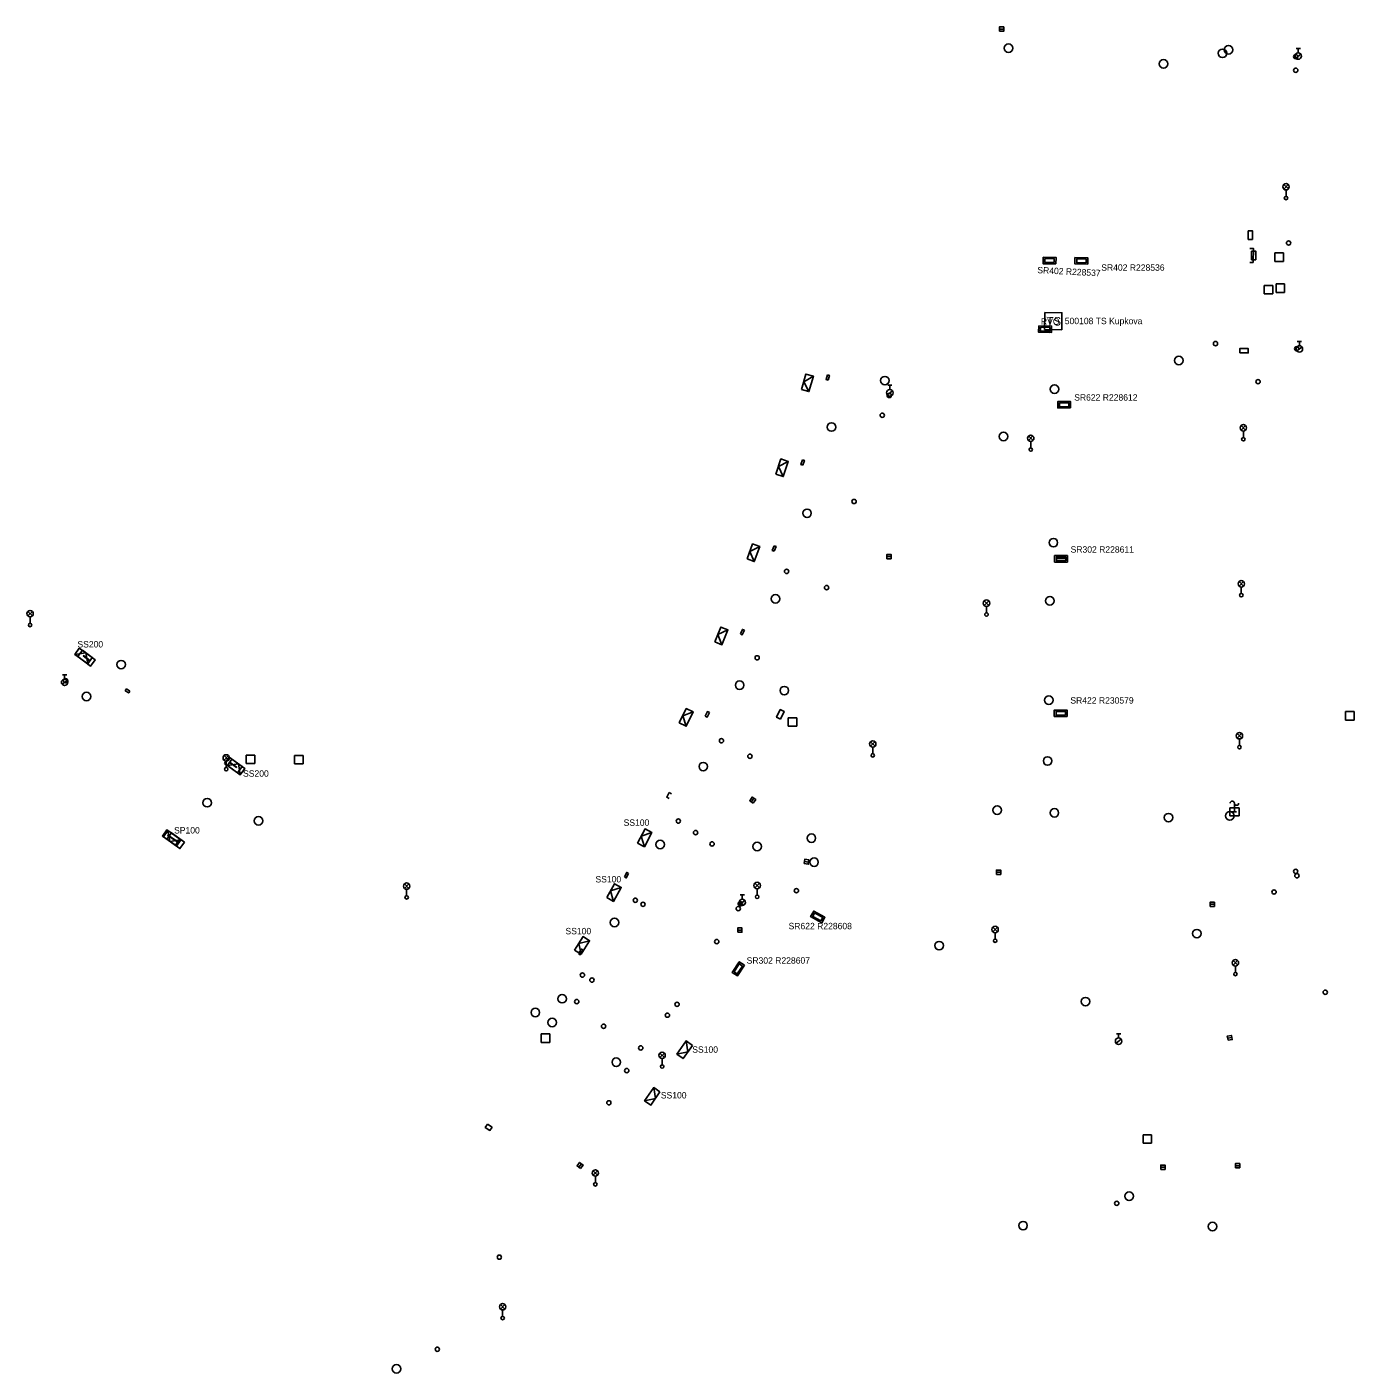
# Model space of a CAD drawing. Extents: x -584388 to -581645, y -1210859 to -1208922.
# Drawn here: x -583175 to -583019.6, y -1210565.7 to -1210408.1 of the extents above; entities that cross this region are included whole.
import ezdxf

# ---------------------------------------------------------------- set-up
doc = ezdxf.new("R2010")
doc.units = 0
for name, color, linetype in [('CIZÍ_NADZEM', 7, 'Continuous'), ('CIZÍ_PODZEM', 7, 'Continuous'), ('ELE_EON', 7, 'Continuous'), ('ELE_EON_POPIS', 7, 'Continuous')]:
    doc.layers.add(name, color=color, linetype=linetype)

msp = doc.modelspace()

# ---------------------------------------------------------------- linework, layer by layer
at = {"layer": 'CIZÍ_NADZEM'}
for p, q in [((-583061.11, -1210408.37), (-583060.61, -1210408.37)), ((-583026.37, -1210410.66), (-583025.87, -1210410.66)), ((-583026.12, -1210411.16), (-583026.12, -1210410.66)), ((-583026.41, -1210411.76), (-583025.82, -1210411.3)), ((-583027.81, -1210427.1), (-583027.29, -1210426.57)), ((-583027.28, -1210427.09), (-583027.81, -1210426.57)), ((-583027.55, -1210427.21), (-583027.55, -1210427.96)), ((-583027.86, -1210434.58), (-583028.86, -1210434.58)), ((-583028.86, -1210434.58), (-583028.86, -1210435.58)), ((-583027.86, -1210435.58), (-583027.86, -1210434.58)), ((-583028.86, -1210435.58), (-583027.86, -1210435.58)), ((-583029.11, -1210438.38), (-583030.11, -1210438.38)), ((-583030.11, -1210438.38), (-583030.11, -1210439.38)), ((-583030.11, -1210439.38), (-583029.11, -1210439.38)), ((-583029.11, -1210439.38), (-583029.11, -1210438.38)), ((-583027.72, -1210438.2), (-583028.72, -1210438.2)), ((-583028.72, -1210438.2), (-583028.72, -1210439.2)), ((-583028.72, -1210439.2), (-583027.72, -1210439.2)), ((-583027.72, -1210439.2), (-583027.72, -1210438.2)), ((-583026.27, -1210446.05), (-583025.68, -1210445.59)), ((-583026.23, -1210444.95), (-583025.73, -1210444.95)), ((-583025.98, -1210445.45), (-583025.98, -1210444.95)), ((-583074.2, -1210450.08), (-583073.7, -1210450.08)), ((-583073.95, -1210450.58), (-583073.95, -1210450.08)), ((-583074.24, -1210451.19), (-583073.65, -1210450.73)), ((-583032.81, -1210455.33), (-583032.29, -1210454.8)), ((-583032.28, -1210455.32), (-583032.81, -1210454.8)), ((-583057.71, -1210456.54), (-583057.19, -1210456.01)), ((-583057.18, -1210456.54), (-583057.71, -1210456.01)), ((-583057.45, -1210456.65), (-583057.45, -1210457.4)), ((-583032.55, -1210455.44), (-583032.55, -1210456.19)), ((-583074.3, -1210470.13), (-583073.8, -1210470.13)), ((-583033.05, -1210473.59), (-583032.53, -1210473.06)), ((-583032.52, -1210473.58), (-583033.05, -1210473.06)), ((-583032.79, -1210473.7), (-583032.79, -1210474.45)), ((-583062.89, -1210475.85), (-583062.37, -1210475.32)), ((-583062.36, -1210475.84), (-583062.89, -1210475.32)), ((-583174.9, -1210477.08), (-583174.38, -1210476.55)), ((-583174.37, -1210477.07), (-583174.9, -1210476.55)), ((-583174.64, -1210477.19), (-583174.64, -1210477.94)), ((-583062.63, -1210475.96), (-583062.63, -1210476.71)), ((-583170.89, -1210485.08), (-583170.3, -1210484.62)), ((-583170.85, -1210483.98), (-583170.35, -1210483.98)), ((-583170.6, -1210484.48), (-583170.6, -1210483.98)), ((-583020.58, -1210488.27), (-583020.58, -1210489.27)), ((-583019.58, -1210488.27), (-583020.58, -1210488.27)), ((-583019.58, -1210489.27), (-583019.58, -1210488.27)), ((-583084.86, -1210489), (-583085.86, -1210489)), ((-583085.86, -1210489), (-583085.86, -1210490)), ((-583085.86, -1210490), (-583084.86, -1210490)), ((-583084.86, -1210490), (-583084.86, -1210489)), ((-583020.58, -1210489.27), (-583019.58, -1210489.27)), ((-583033.27, -1210491.38), (-583032.75, -1210490.85)), ((-583032.74, -1210491.38), (-583033.27, -1210490.85)), ((-583033.01, -1210491.49), (-583033.01, -1210492.24)), ((-583076.21, -1210492.34), (-583075.69, -1210491.81)), ((-583075.68, -1210492.33), (-583076.21, -1210491.81)), ((-583075.95, -1210492.45), (-583075.95, -1210493.2)), ((-583151.93, -1210493.96), (-583151.41, -1210493.43)), ((-583151.4, -1210493.96), (-583151.93, -1210493.43)), ((-583151.67, -1210494.07), (-583151.67, -1210494.82)), ((-583148.34, -1210493.36), (-583149.34, -1210493.36)), ((-583149.34, -1210493.36), (-583149.34, -1210494.36)), ((-583149.34, -1210494.36), (-583148.34, -1210494.36)), ((-583148.34, -1210494.36), (-583148.34, -1210493.36)), ((-583142.68, -1210493.41), (-583143.68, -1210493.41)), ((-583143.68, -1210493.41), (-583143.68, -1210494.41)), ((-583143.68, -1210494.41), (-583142.68, -1210494.41)), ((-583142.68, -1210494.41), (-583142.68, -1210493.41)), ((-583090.15, -1210498.85), (-583089.87, -1210498.43)), ((-583033.6, -1210500), (-583033.6, -1210499)), ((-583033.85, -1210500), (-583033.35, -1210500)), ((-583083.96, -1210505.82), (-583083.46, -1210505.9)), ((-583061.46, -1210507.09), (-583060.96, -1210507.09)), ((-583130.8, -1210508.97), (-583130.28, -1210508.44)), ((-583130.27, -1210508.97), (-583130.8, -1210508.44)), ((-583089.75, -1210508.9), (-583089.23, -1210508.37)), ((-583089.22, -1210508.9), (-583089.75, -1210508.37)), ((-583130.54, -1210509.08), (-583130.54, -1210509.83)), ((-583091.52, -1210510.84), (-583090.93, -1210510.38)), ((-583091.48, -1210509.74), (-583090.98, -1210509.74)), ((-583091.23, -1210510.24), (-583091.23, -1210509.74)), ((-583089.49, -1210509.01), (-583089.49, -1210509.76)), ((-583036.44, -1210510.84), (-583035.94, -1210510.84)), ((-583061.88, -1210514.05), (-583061.36, -1210513.52)), ((-583061.35, -1210514.05), (-583061.88, -1210513.52)), ((-583091.77, -1210513.86), (-583091.27, -1210513.86)), ((-583061.62, -1210514.16), (-583061.62, -1210514.91)), ((-583033.74, -1210517.95), (-583033.22, -1210517.42)), ((-583033.21, -1210517.95), (-583033.74, -1210517.42)), ((-583033.48, -1210518.06), (-583033.48, -1210518.81)), ((-583113.77, -1210526.01), (-583114.77, -1210526.01)), ((-583114.77, -1210526.01), (-583114.77, -1210527.01)), ((-583113.77, -1210527.01), (-583113.77, -1210526.01)), ((-583047.41, -1210525.99), (-583046.91, -1210525.99)), ((-583047.16, -1210526.49), (-583047.16, -1210525.99)), ((-583114.77, -1210527.01), (-583113.77, -1210527.01)), ((-583047.45, -1210527.09), (-583046.86, -1210526.63)), ((-583034.39, -1210526.52), (-583033.89, -1210526.42)), ((-583100.88, -1210528.78), (-583100.36, -1210528.25)), ((-583100.35, -1210528.78), (-583100.88, -1210528.25)), ((-583100.62, -1210528.89), (-583100.62, -1210529.64)), ((-583043.29, -1210537.82), (-583044.29, -1210537.82)), ((-583044.29, -1210537.82), (-583044.29, -1210538.82)), ((-583044.29, -1210538.82), (-583043.29, -1210538.82)), ((-583043.29, -1210538.82), (-583043.29, -1210537.82)), ((-583110.38, -1210541.61), (-583110.08, -1210541.21)), ((-583108.7, -1210542.56), (-583108.18, -1210542.03)), ((-583108.17, -1210542.56), (-583108.7, -1210542.03)), ((-583042.22, -1210541.62), (-583041.72, -1210541.62)), ((-583033.48, -1210541.44), (-583032.98, -1210541.44)), ((-583108.44, -1210542.67), (-583108.44, -1210543.42)), ((-583119.56, -1210558.22), (-583119.04, -1210557.69)), ((-583119.03, -1210558.22), (-583119.56, -1210557.69)), ((-583119.3, -1210558.33), (-583119.3, -1210559.08))]:
    msp.add_line(p, q, dxfattribs=at)
for points in [[(-583061.11, -1210408.62), (-583060.61, -1210408.62), (-583060.61, -1210408.12), (-583061.11, -1210408.12)], [(-583031.47, -1210433), (-583031.47, -1210432), (-583031.97, -1210432), (-583031.97, -1210433)], [(-583031.08, -1210435.38), (-583031.08, -1210434.38), (-583031.58, -1210434.38), (-583031.58, -1210435.38)], [(-583032.97, -1210446.28), (-583031.97, -1210446.28), (-583031.97, -1210445.78), (-583032.97, -1210445.78)], [(-583074.3, -1210470.38), (-583073.8, -1210470.38), (-583073.8, -1210469.88), (-583074.3, -1210469.88)], [(-583086.77, -1210489.16), (-583086.34, -1210488.26), (-583086.79, -1210488.04), (-583087.22, -1210488.94)], [(-583089.94, -1210498.99), (-583089.66, -1210498.57), (-583090.08, -1210498.29), (-583090.36, -1210498.71)], [(-583084, -1210506.07), (-583083.5, -1210506.15), (-583083.42, -1210505.65), (-583083.92, -1210505.57)], [(-583061.46, -1210507.34), (-583060.96, -1210507.34), (-583060.96, -1210506.84), (-583061.46, -1210506.84)], [(-583036.44, -1210511.09), (-583035.94, -1210511.09), (-583035.94, -1210510.59), (-583036.44, -1210510.59)], [(-583091.77, -1210514.11), (-583091.27, -1210514.11), (-583091.27, -1210513.61), (-583091.77, -1210513.61)], [(-583034.34, -1210526.76), (-583033.85, -1210526.67), (-583033.94, -1210526.18), (-583034.43, -1210526.27)], [(-583110.18, -1210541.76), (-583109.88, -1210541.36), (-583110.28, -1210541.06), (-583110.58, -1210541.46)], [(-583042.22, -1210541.87), (-583041.72, -1210541.87), (-583041.72, -1210541.37), (-583042.22, -1210541.37)], [(-583033.48, -1210541.69), (-583032.98, -1210541.69), (-583032.98, -1210541.19), (-583033.48, -1210541.19)]]:
    msp.add_lwpolyline(points, close=True, dxfattribs=at)
for points in [[(-583031.38, -1210435.71), (-583031.37, -1210434.05), (-583031.78, -1210434.05)], [(-583031.38, -1210435.71), (-583031.79, -1210435.71)], [(-583056.31, -1210443.54), (-583056.32, -1210443.86), (-583055.25, -1210443.89)], [(-583055.24, -1210443.56), (-583055.25, -1210443.89)], [(-583081.26, -1210448.85), (-583081.42, -1210449.4), (-583081.18, -1210449.47)], [(-583081.26, -1210448.85), (-583081.02, -1210448.92), (-583081.18, -1210449.47)], [(-583084.19, -1210458.79), (-583084.37, -1210459.35), (-583084.13, -1210459.43)], [(-583084.19, -1210458.79), (-583083.95, -1210458.87), (-583084.13, -1210459.43)], [(-583087.51, -1210468.87), (-583087.72, -1210469.41), (-583087.49, -1210469.5)], [(-583087.51, -1210468.87), (-583087.28, -1210468.96), (-583087.49, -1210469.5)], [(-583054.36, -1210470.36), (-583054.36, -1210470.01)], [(-583053.27, -1210470.02), (-583054.36, -1210470.01)], [(-583053.27, -1210470.37), (-583054.36, -1210470.36)], [(-583091.46, -1210479.19), (-583091.22, -1210478.65), (-583090.99, -1210478.75)], [(-583091.46, -1210479.19), (-583091.23, -1210479.29), (-583090.99, -1210478.75)], [(-583095.57, -1210488.82), (-583095.31, -1210488.28), (-583095.09, -1210488.39)], [(-583095.57, -1210488.82), (-583095.35, -1210488.93), (-583095.09, -1210488.39)], [(-583099.79, -1210497.75), (-583100.07, -1210498.3), (-583099.79, -1210498.44)], [(-583099.79, -1210497.75), (-583099.51, -1210497.89)], [(-583105.04, -1210507.62), (-583104.76, -1210507.1), (-583104.54, -1210507.22)], [(-583105.04, -1210507.62), (-583104.82, -1210507.74), (-583104.54, -1210507.22)], [(-583110.41, -1210516.61), (-583110.08, -1210516.09), (-583109.87, -1210516.22)], [(-583110.41, -1210516.61), (-583110.2, -1210516.74), (-583109.87, -1210516.22)]]:
    msp.add_lwpolyline(points, dxfattribs=at)
for centre, radius in [((-583060.05, -1210410.61), 0.5), ((-583034.99, -1210411.21), 0.5), ((-583034.29, -1210410.79), 0.5), ((-583026.12, -1210411.53), 0.375), ((-583041.89, -1210412.45), 0.5), ((-583026.42, -1210411.59), 0.25), ((-583026.41, -1210413.19), 0.25), ((-583027.55, -1210426.83), 0.375), ((-583027.55, -1210428.16), 0.2), ((-583027.25, -1210433.42), 0.25), ((-583035.81, -1210445.19), 0.25), ((-583026.3, -1210445.8), 0.25), ((-583025.98, -1210445.82), 0.375), ((-583040.11, -1210447.17), 0.5), ((-583074.53, -1210449.53), 0.5), ((-583073.95, -1210450.96), 0.375), ((-583054.67, -1210450.52), 0.5), ((-583030.82, -1210449.65), 0.25), ((-583074.02, -1210451.27), 0.25), ((-583074.84, -1210453.58), 0.25), ((-583080.78, -1210454.96), 0.5), ((-583032.55, -1210455.06), 0.375), ((-583060.64, -1210456.06), 0.5), ((-583057.45, -1210456.28), 0.375), ((-583032.55, -1210456.39), 0.2), ((-583057.45, -1210457.6), 0.2), ((-583083.65, -1210465.06), 0.5), ((-583078.14, -1210463.68), 0.25), ((-583054.8, -1210468.5), 0.5), ((-583086.04, -1210471.86), 0.25), ((-583081.36, -1210473.76), 0.25), ((-583032.79, -1210473.32), 0.375), ((-583087.35, -1210475.08), 0.5), ((-583062.63, -1210475.58), 0.375), ((-583055.21, -1210475.3), 0.5), ((-583032.79, -1210474.65), 0.2), ((-583174.64, -1210476.81), 0.375), ((-583062.63, -1210476.91), 0.2), ((-583174.64, -1210478.14), 0.2), ((-583089.49, -1210481.98), 0.25), ((-583163.98, -1210482.78), 0.5), ((-583170.6, -1210484.85), 0.375), ((-583170.49, -1210484.66), 0.25), ((-583091.54, -1210485.19), 0.5), ((-583168.04, -1210486.51), 0.5), ((-583086.31, -1210485.82), 0.5), ((-583055.34, -1210486.94), 0.5), ((-583093.67, -1210491.69), 0.25), ((-583033.01, -1210491.11), 0.375), ((-583075.95, -1210492.07), 0.375), ((-583033.01, -1210492.44), 0.2), ((-583151.67, -1210493.7), 0.375), ((-583095.8, -1210494.72), 0.5), ((-583090.34, -1210493.5), 0.25), ((-583075.95, -1210493.4), 0.2), ((-583055.47, -1210494.06), 0.5), ((-583151.67, -1210495.02), 0.2), ((-583153.9, -1210498.94), 0.5), ((-583061.37, -1210499.81), 0.5), ((-583147.89, -1210501.06), 0.5), ((-583098.72, -1210501.1), 0.25), ((-583054.68, -1210500.13), 0.5), ((-583041.31, -1210500.69), 0.5), ((-583034.14, -1210500.49), 0.5), ((-583096.7, -1210502.44), 0.25), ((-583083.14, -1210503.1), 0.5), ((-583100.86, -1210503.83), 0.5), ((-583094.77, -1210503.77), 0.25), ((-583089.48, -1210504.07), 0.5), ((-583082.83, -1210505.9), 0.5), ((-583026.42, -1210506.99), 0.25), ((-583026.28, -1210507.5), 0.25), ((-583130.54, -1210508.71), 0.375), ((-583089.49, -1210508.64), 0.375), ((-583130.54, -1210510.03), 0.2), ((-583103.76, -1210510.36), 0.25), ((-583091.23, -1210510.61), 0.375), ((-583089.49, -1210509.96), 0.2), ((-583084.89, -1210509.24), 0.25), ((-583028.95, -1210509.4), 0.25), ((-583102.86, -1210510.84), 0.25), ((-583091.71, -1210511.34), 0.25), ((-583091.47, -1210510.78), 0.25), ((-583106.2, -1210512.96), 0.5), ((-583061.62, -1210513.79), 0.375), ((-583094.22, -1210515.2), 0.25), ((-583068.18, -1210515.68), 0.5), ((-583061.62, -1210515.11), 0.2), ((-583037.99, -1210514.27), 0.5), ((-583033.48, -1210517.69), 0.375), ((-583109.95, -1210519.13), 0.25), ((-583108.84, -1210519.71), 0.25), ((-583033.48, -1210519.01), 0.2), ((-583112.33, -1210521.89), 0.5), ((-583022.96, -1210521.13), 0.25), ((-583115.47, -1210523.5), 0.5), ((-583110.62, -1210522.23), 0.25), ((-583098.87, -1210522.55), 0.25), ((-583051.03, -1210522.23), 0.5), ((-583113.5, -1210524.67), 0.5), ((-583100, -1210523.82), 0.25), ((-583107.48, -1210525.12), 0.25), ((-583103.12, -1210527.65), 0.25), ((-583047.16, -1210526.86), 0.375), ((-583105.99, -1210529.33), 0.5), ((-583100.62, -1210528.52), 0.375), ((-583104.76, -1210530.31), 0.25), ((-583100.62, -1210529.84), 0.2), ((-583106.86, -1210534.08), 0.25), ((-583108.44, -1210542.3), 0.375), ((-583108.44, -1210543.62), 0.2), ((-583045.93, -1210545.02), 0.5), ((-583047.38, -1210545.85), 0.25), ((-583058.35, -1210548.46), 0.5), ((-583036.16, -1210548.57), 0.5), ((-583119.69, -1210552.15), 0.25), ((-583119.3, -1210557.96), 0.375), ((-583119.3, -1210559.28), 0.2), ((-583126.95, -1210562.93), 0.25), ((-583131.73, -1210565.22), 0.5)]:
    msp.add_circle(centre, radius, dxfattribs=at)
for centre, start, end in [((-583033.85, -1210499), 0, 180), ((-583033.35, -1210499), 180, 0)]:
    msp.add_arc(centre, 0.25, start, end, dxfattribs=at)
at = {"layer": 'CIZÍ_PODZEM'}
for points in [[(-583163.49, -1210485.83), (-583163.35, -1210485.62), (-583162.95, -1210485.89)], [(-583163.49, -1210485.83), (-583163.09, -1210486.1), (-583162.95, -1210485.89)], [(-583034.15, -1210499.55), (-583033.05, -1210499.53)], [(-583034.15, -1210499.55), (-583034.14, -1210500.49)], [(-583033.04, -1210500.47), (-583034.14, -1210500.49)], [(-583033.05, -1210499.53), (-583033.04, -1210500.47)], [(-583120.54, -1210536.94), (-583120.79, -1210537.32), (-583121.33, -1210536.96), (-583121.08, -1210536.58)], [(-583120.54, -1210536.94), (-583121.08, -1210536.58)]]:
    msp.add_lwpolyline(points, dxfattribs=at)
at = {"layer": 'ELE_EON'}
for points in [[(-583054.5, -1210435.86), (-583056, -1210435.84), (-583055.99, -1210435.09), (-583054.49, -1210435.11)], [(-583054.7, -1210435.71), (-583055.8, -1210435.69), (-583055.79, -1210435.24), (-583054.69, -1210435.26)], [(-583050.78, -1210435.89), (-583052.28, -1210435.87), (-583052.27, -1210435.12), (-583050.77, -1210435.14)], [(-583050.97, -1210435.73), (-583052.07, -1210435.73), (-583052.07, -1210435.28), (-583050.97, -1210435.28)], [(-583055.82, -1210443.56), (-583053.82, -1210443.58), (-583053.79, -1210441.58), (-583055.79, -1210441.56)], [(-583056.51, -1210443.11), (-583055.01, -1210443.15), (-583055.03, -1210443.9), (-583056.53, -1210443.86)], [(-583056.32, -1210443.27), (-583055.22, -1210443.29), (-583055.23, -1210443.74), (-583056.33, -1210443.72)], [(-583084.29, -1210450.57), (-583083.78, -1210448.77), (-583082.91, -1210449.02), (-583083.43, -1210450.82)], [(-583052.78, -1210452.73), (-583054.28, -1210452.73), (-583054.28, -1210451.98), (-583052.78, -1210451.98)], [(-583052.98, -1210452.58), (-583054.08, -1210452.58), (-583054.08, -1210452.13), (-583052.98, -1210452.13)], [(-583087.29, -1210460.48), (-583086.71, -1210458.7), (-583085.85, -1210458.98), (-583086.43, -1210460.76)], [(-583090.68, -1210470.41), (-583090.03, -1210468.65), (-583089.18, -1210468.96), (-583089.84, -1210470.72)], [(-583053.15, -1210470.77), (-583054.65, -1210470.77), (-583054.65, -1210470.02), (-583053.15, -1210470.02)], [(-583053.35, -1210470.62), (-583054.45, -1210470.62), (-583054.45, -1210470.17), (-583053.35, -1210470.17)], [(-583094.45, -1210480.12), (-583093.74, -1210478.38), (-583092.91, -1210478.72), (-583093.61, -1210480.46)], [(-583168.88, -1210480.85), (-583167.36, -1210481.95), (-583167.89, -1210482.68), (-583169.41, -1210481.58)], [(-583169.06, -1210481.82), (-583167.56, -1210482.94), (-583167.02, -1210482.22), (-583168.52, -1210481.1)], [(-583168.43, -1210481.75), (-583167.68, -1210482.32), (-583167.65, -1210482.29), (-583168.4, -1210481.72)], [(-583098.61, -1210489.61), (-583097.8, -1210487.92), (-583096.99, -1210488.3), (-583097.79, -1210490)], [(-583053.19, -1210488.85), (-583054.69, -1210488.85), (-583054.69, -1210488.1), (-583053.19, -1210488.1)], [(-583053.39, -1210488.7), (-583054.49, -1210488.7), (-583054.49, -1210488.25), (-583053.39, -1210488.25)], [(-583151.86, -1210494.34), (-583150.34, -1210495.44), (-583149.81, -1210494.71), (-583151.33, -1210493.61)], [(-583151.01, -1210493.85), (-583149.49, -1210494.95), (-583150.02, -1210495.68), (-583151.54, -1210494.58)], [(-583151.23, -1210494.27), (-583150.47, -1210494.81), (-583150.45, -1210494.78), (-583151.21, -1210494.24)], [(-583157.1, -1210503.18), (-583158.64, -1210502.12), (-583159.15, -1210502.86), (-583157.61, -1210503.92)], [(-583157.5, -1210504.02), (-583159.03, -1210502.92), (-583158.5, -1210502.19), (-583156.98, -1210503.29)], [(-583156.57, -1210503.57), (-583158.09, -1210502.49), (-583158.62, -1210503.22), (-583157.09, -1210504.31)], [(-583103.49, -1210503.68), (-583102.62, -1210502.02), (-583101.82, -1210502.44), (-583102.7, -1210504.1)], [(-583157.73, -1210503.27), (-583158.5, -1210502.74), (-583158.52, -1210502.77), (-583157.75, -1210503.3)], [(-583157.2, -1210503.65), (-583157.96, -1210503.11), (-583157.98, -1210503.14), (-583157.22, -1210503.68)], [(-583107.11, -1210510.06), (-583106.19, -1210508.43), (-583105.41, -1210508.87), (-583106.33, -1210510.51)], [(-583081.92, -1210513.01), (-583083.23, -1210512.28), (-583082.87, -1210511.63), (-583081.55, -1210512.35)], [(-583082.02, -1210512.78), (-583082.98, -1210512.25), (-583082.76, -1210511.85), (-583081.8, -1210512.39)], [(-583110.88, -1210516.2), (-583109.87, -1210514.62), (-583109.12, -1210515.1), (-583110.12, -1210516.68)], [(-583090.97, -1210517.98), (-583091.8, -1210519.23), (-583092.43, -1210518.81), (-583091.59, -1210517.57)], [(-583091.21, -1210518.07), (-583091.82, -1210518.98), (-583092.19, -1210518.73), (-583091.58, -1210517.82)], [(-583097.07, -1210527.36), (-583098.16, -1210528.9), (-583098.89, -1210528.38), (-583097.81, -1210526.84)], [(-583100.87, -1210532.81), (-583101.93, -1210534.35), (-583102.67, -1210533.84), (-583101.61, -1210532.3)]]:
    msp.add_lwpolyline(points, close=True, dxfattribs=at)
for points in [[(-583083.43, -1210450.82), (-583084.04, -1210449.67), (-583082.91, -1210449.02)], [(-583086.43, -1210460.76), (-583087, -1210459.59), (-583085.85, -1210458.98)], [(-583089.84, -1210470.72), (-583090.35, -1210469.53), (-583089.18, -1210468.96)], [(-583093.61, -1210480.46), (-583094.09, -1210479.25), (-583092.91, -1210478.72)], [(-583169.41, -1210481.58), (-583168.12, -1210481.4), (-583167.89, -1210482.68)], [(-583097.79, -1210490), (-583098.2, -1210488.76), (-583096.99, -1210488.3)], [(-583151.54, -1210494.58), (-583150.25, -1210494.4), (-583150.02, -1210495.68)], [(-583156.98, -1210503.29), (-583158.26, -1210503.47), (-583158.5, -1210502.19)], [(-583102.7, -1210504.1), (-583103.06, -1210502.85), (-583101.82, -1210502.44)], [(-583106.33, -1210510.51), (-583106.65, -1210509.25), (-583105.41, -1210508.87)], [(-583110.12, -1210516.68), (-583110.38, -1210515.41), (-583109.12, -1210515.1)], [(-583097.81, -1210526.84), (-583097.62, -1210528.13), (-583098.89, -1210528.38)], [(-583101.61, -1210532.3), (-583101.4, -1210533.58), (-583102.67, -1210533.84)]]:
    msp.add_lwpolyline(points, dxfattribs=at)

# ---------------------------------------------------------------- texts
msp.add_text('TS', height=1, rotation=359.1816, dxfattribs=at).set_placement((-583055.61, -1210443.06))
at = {"layer": 'ELE_EON_POPIS'}
msp.add_text('SR402 R228537', height=0.75, rotation=357.1594, dxfattribs=at).set_placement((-583056.69, -1210436.95))
for s, p in [('SR402 R228536', (-583049.19, -1210436.67)), ('RVO', (-583056.25, -1210442.98)), ('500108 TS Kupkova', (-583053.46, -1210442.92)), ('SR622 R228612', (-583052.36, -1210451.87)), ('SR302 R228611', (-583052.78, -1210469.67)), ('SS200', (-583169.1, -1210480.77)), ('SR422 R230579', (-583052.81, -1210487.34)), ('SS200', (-583149.7, -1210495.9)), ('SS100', (-583105.13, -1210501.65)), ('SP100', (-583157.78, -1210502.55)), ('SS100', (-583108.43, -1210508.28)), ('SS100', (-583111.94, -1210514.35)), ('SR622 R228608', (-583085.81, -1210513.76)), ('SR302 R228607', (-583090.72, -1210517.79)), ('SS100', (-583097.09, -1210528.22)), ('SS100', (-583100.77, -1210533.57))]:
    msp.add_text(s, height=0.75, dxfattribs=at).set_placement(p)

doc.saveas('drawing.dxf')
